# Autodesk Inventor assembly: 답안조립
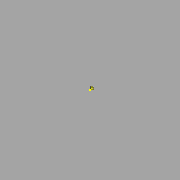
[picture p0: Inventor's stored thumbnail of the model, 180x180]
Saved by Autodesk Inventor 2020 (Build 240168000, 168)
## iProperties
Created: 2021-11
Part Number: 답안조립
Document SubType Name: Assembly
Designer: Administrator
Author: Administrator
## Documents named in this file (14)
- C:\Users\Administrator\Desktop\711106V1032\답안조립.iam
- C:\Users\Administrator\Desktop\711106V1032\본체.ipt
- C:\Users\Administrator\Desktop\711106V1032\베어링 6205.ipt
- 베어링 6205.ipt
- C:\Users\Administrator\Desktop\711106V1032\볼트 M4x0.7.ipt
- C:\Users\Administrator\Desktop\711106V1032\부시.ipt
- C:\Users\Administrator\Desktop\711106V1032\상부커버.ipt
- C:\Users\Administrator\Desktop\711106V1032\슬라이드 커버.ipt
- C:\Users\Administrator\Desktop\711106V1032\슬라이드.ipt
- C:\Users\Administrator\Desktop\711106V1032\오일실.ipt
- 오일실.ipt
- C:\Users\Administrator\Desktop\711106V1032\육각머리볼트 M4.ipt
- C:\Users\Administrator\Desktop\711106V1032\축 커버.ipt
- C:\Users\Administrator\Desktop\711106V1032\편심축.ipt
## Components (21 placed, 1 different names)
1. M4x0.7:6
2. M4x0.7:5 — 각도:1
3. M4x0.7:19
4. M4x0.7:20
5. M4x0.7:21
6. M4x0.7:1
7. M4x0.7:2
8. M4x0.7:3
9. M4x0.7:4
10. M4x0.7:7
11. M4x0.7:8
12. M4x0.7:9
13. M4x0.7:10
14. M4x0.7:11
15. M4x0.7:12
16. M4x0.7:13
17. M4x0.7:14
18. M4x0.7:15
19. M4x0.7:16
20. M4x0.7:17
21. M4x0.7:18
## Component patterns: 구성요소 패턴 1:2 (4 elements), 구성요소 패턴 1:3 (4 elements), 구성요소 패턴 1:4 (4 elements)
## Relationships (1: Angle 1)
- 각도:1 [Angle]: M4x0.7:5
